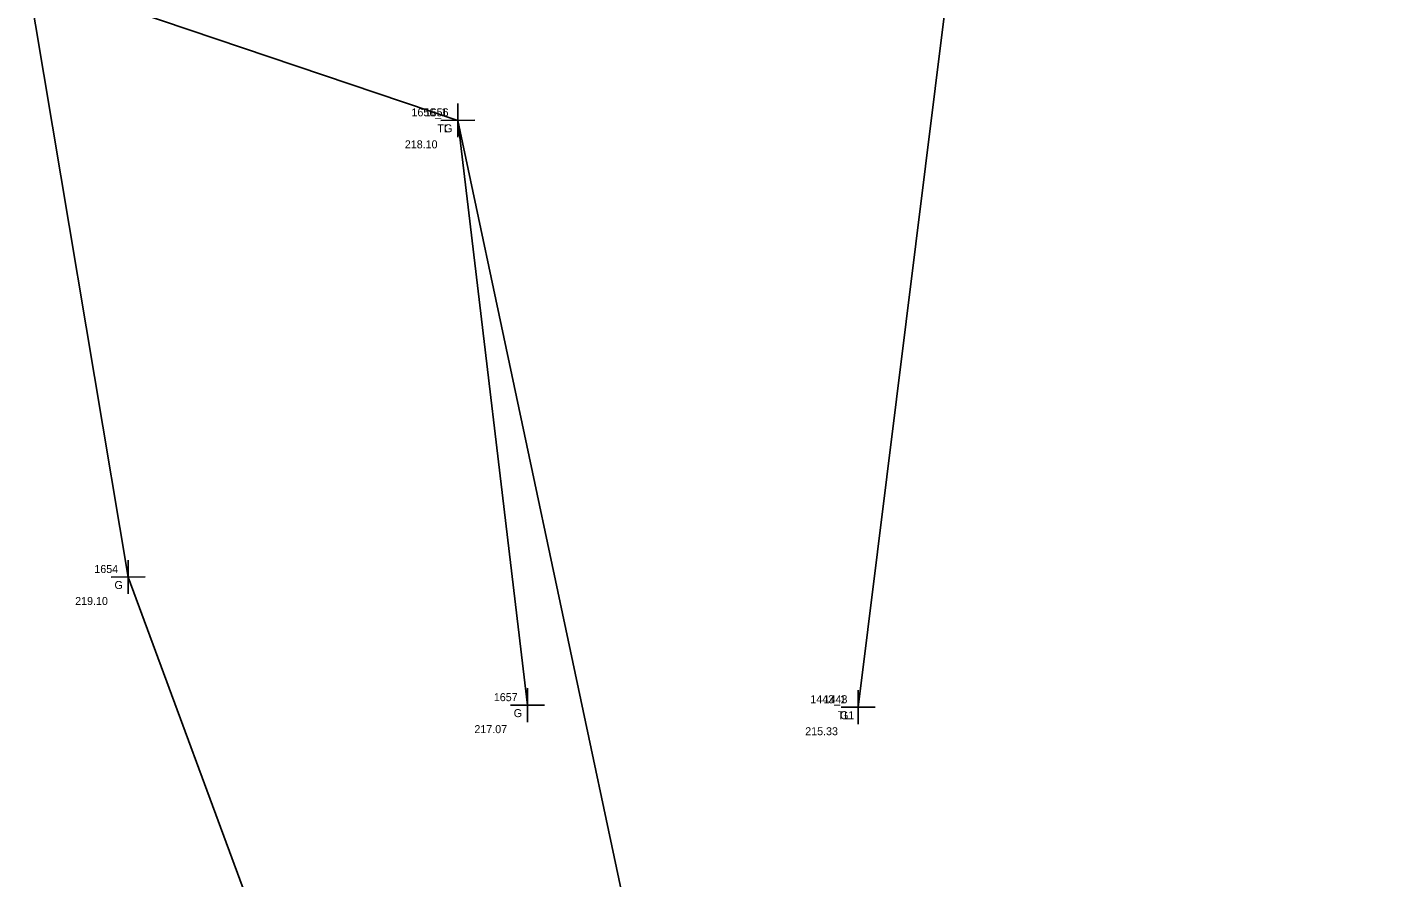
# Model space of a CAD drawing. Extents: x 1158983 to 1160032, y 610902 to 611573.
# Drawn here: x 1159291.3 to 1159342.2, y 611317.7 to 611349.6 of the extents above; entities that cross this region are included whole.
import ezdxf

# ---------------------------------------------------------------- set-up
doc = ezdxf.new("R2010")
doc.units = 0
for name, color, linetype in [('S_Field_Code', 7, 'Continuous'), ('S_Ground_Elevation', 7, 'Continuous'), ('S_Point_Elevation', 7, 'Continuous'), ('S_Point_Name', 7, 'Continuous'), ('S_Survey_Shot', 7, 'Continuous'), ('S_Trees_TreeLine', 7, 'Continuous')]:
    doc.layers.add(name, color=color, linetype=linetype)

msp = doc.modelspace()

# ---------------------------------------------------------------- linework, layer by layer
at = {"layer": 'S_Ground_Elevation'}
for points in [[(1159320.582, 611391.413), (1159326.464, 611355.944), (1159322.505, 611324.086)], [(1159352.149, 611311.344), (1159339.531, 611314.728), (1159324.665, 611314.427), (1159313.821, 611316.237), (1159300.045, 611315.663), (1159295.131, 611328.971), (1159291.342, 611351.557), (1159307.492, 611346.1), (1159310.1, 611324.164)]]:
    msp.add_lwpolyline(points, dxfattribs=at)
at = {"layer": 'S_Survey_Shot'}
for p, q in [((1159307.494, 611345.464), (1159307.491, 611346.736)), ((1159307.494, 611345.464), (1159307.491, 611346.736)), ((1159306.856, 611346.099), (1159308.129, 611346.101)), ((1159306.856, 611346.099), (1159308.129, 611346.101)), ((1159307.492, 611346.1), (1159307.492, 611346.1)), ((1159307.492, 611346.1), (1159307.492, 611346.1)), ((1159295.133, 611328.335), (1159295.13, 611329.607)), ((1159294.495, 611328.97), (1159295.768, 611328.973)), ((1159295.131, 611328.971), (1159295.131, 611328.971)), ((1159310.101, 611323.528), (1159310.098, 611324.801)), ((1159322.506, 611323.45), (1159322.503, 611324.722)), ((1159322.506, 611323.45), (1159322.503, 611324.722)), ((1159309.463, 611324.163), (1159310.736, 611324.166)), ((1159310.1, 611324.164), (1159310.1, 611324.164)), ((1159321.868, 611324.085), (1159323.141, 611324.087)), ((1159321.868, 611324.085), (1159323.141, 611324.087)), ((1159322.505, 611324.086), (1159322.505, 611324.086)), ((1159322.505, 611324.086), (1159322.505, 611324.086))]:
    msp.add_line(p, q, dxfattribs=at)
at = {"layer": 'S_Trees_TreeLine'}
for points in [[(1159320.582, 611391.413), (1159326.464, 611355.944), (1159322.505, 611324.086)], [(1159313.821, 611316.237), (1159307.492, 611346.1)]]:
    msp.add_lwpolyline(points, dxfattribs=at)

# ---------------------------------------------------------------- texts
at = {"layer": 'S_Field_Code'}
for s, p in [('TL', (1159306.72, 611345.65)), ('G', (1159306.977, 611345.65)), ('G', (1159294.617, 611328.521)), ('G', (1159309.585, 611323.715)), ('TL', (1159321.732, 611323.636)), ('G1', (1159321.82, 611323.636))]:
    msp.add_text(s, height=0.3, dxfattribs=at).set_placement(p)
at = {"layer": 'S_Point_Elevation'}
for s, p in [('218.10', (1159305.503, 611345.05)), ('218.10', (1159305.503, 611345.05)), ('219.10', (1159293.143, 611327.921)), ('217.07', (1159308.111, 611323.114)), ('215.33', (1159320.516, 611323.036)), ('215.33', (1159320.516, 611323.036))]:
    msp.add_text(s, height=0.3, dxfattribs=at).set_placement(p)
at = {"layer": 'S_Point_Name'}
for s, p in [('1656_1', (1159305.752, 611346.25)), ('1656', (1159306.25, 611346.25)), ('1654', (1159293.861, 611329.121)), ('1657', (1159308.841, 611324.314)), ('1443_1', (1159320.707, 611324.236)), ('1443', (1159321.206, 611324.236))]:
    msp.add_text(s, height=0.3, dxfattribs=at).set_placement(p)

doc.saveas('drawing.dxf')
